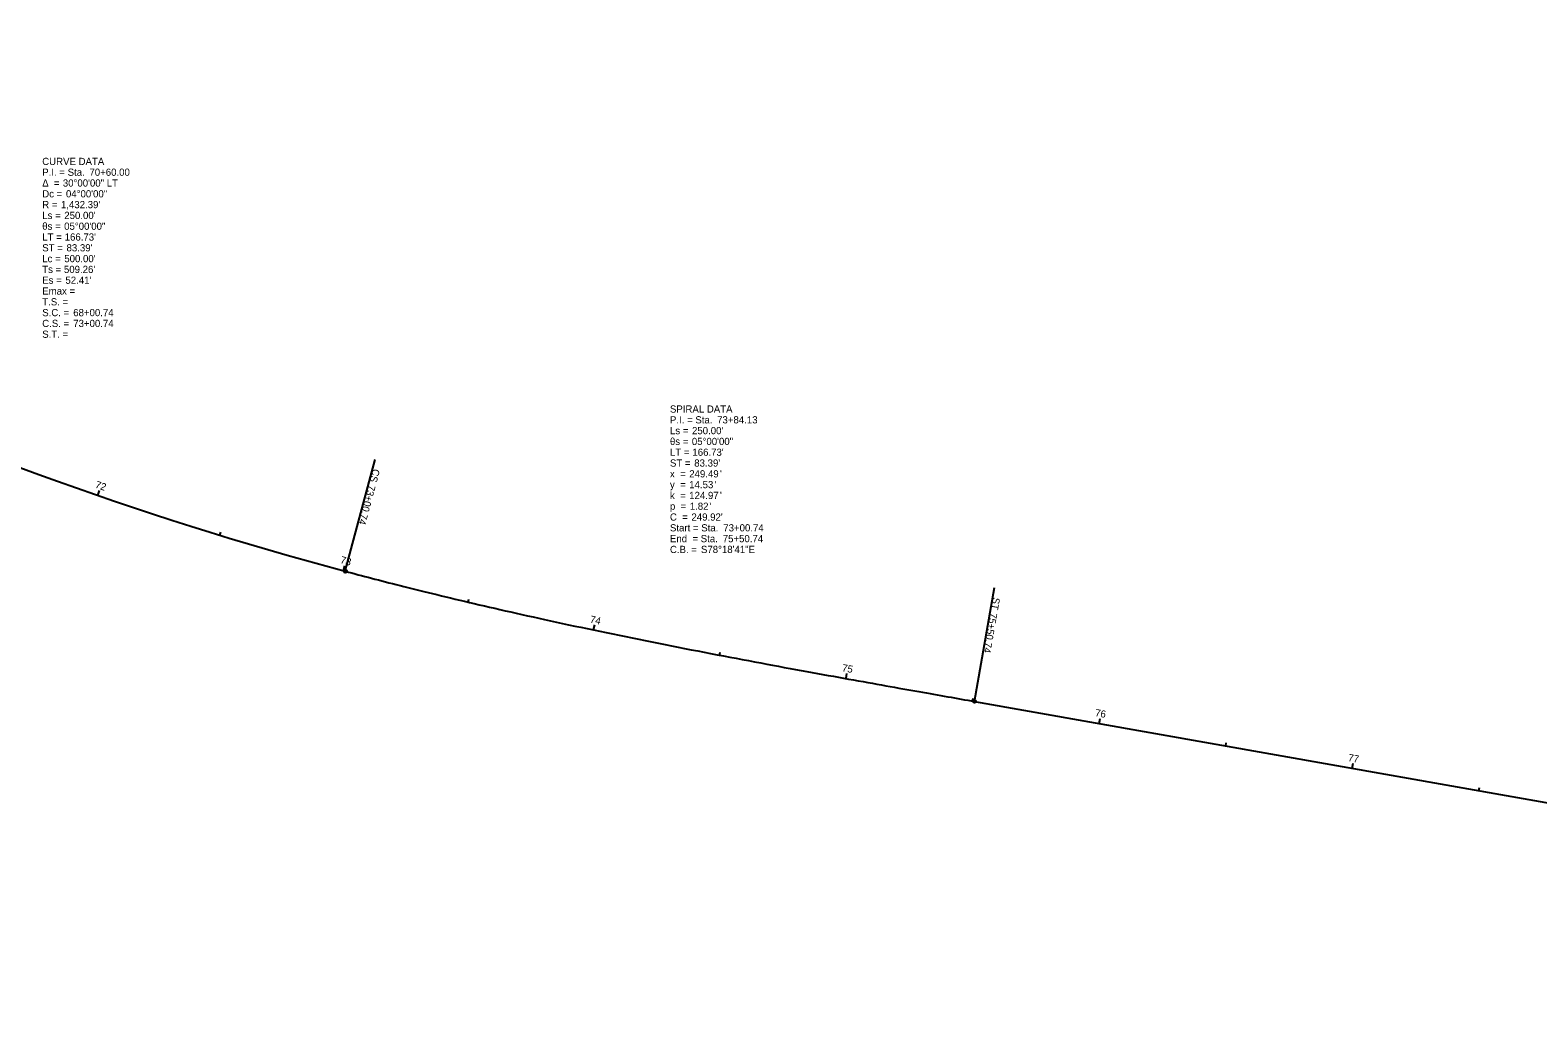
# Model space of a CAD drawing. Extents: x 1999336 to 2003366, y 252766 to 253936.
# Drawn here: x 1999900 to 2000486, y 253329 to 253714 of the extents above; entities that cross this region are included whole.
import ezdxf

# ---------------------------------------------------------------- set-up
doc = ezdxf.new("R2010")
doc.units = 0
for name, color, linetype in [('GE_X_CL_20', 7, 'Continuous'), ('GK_Visualization', 7, 'Continuous'), ('RW_X_Esmt_SH', 7, 'Continuous'), ('SC_Scratch3', 7, 'Continuous'), ('SV_X_Control_Cells_Found', 7, 'Continuous'), ('SV_X_Text_Elevation', 7, 'Continuous'), ('SV_X_Text_Name', 7, 'Continuous')]:
    doc.layers.add(name, color=color, linetype=linetype)

msp = doc.modelspace()

# ---------------------------------------------------------------- linework, layer by layer
at = {"layer": 'GE_X_CL_20'}
for p, q in [((2000022.52, 253503.8), (2000034.18, 253547.26)), ((1999926.22, 253533.31), (1999926.61, 253534.44)), ((2000021.81, 253503.99), (2000022.12, 253505.15)), ((2000267.25, 253453.17), (2000275.08, 253497.48)), ((2000119.11, 253480.97), (2000119.35, 253482.14)), ((2000217.3, 253462.06), (2000217.66, 253464.03)), ((2000315.76, 253444.6), (2000315.97, 253445.78)), ((2000414.24, 253427.2), (2000414.45, 253428.38))]:
    msp.add_line(p, q, dxfattribs=at)
for centre in [(2000022.52, 253503.8), (2000267.25, 253453.17)]:
    msp.add_circle(centre, 0.6, dxfattribs=at)
at = {"layer": 'GK_Visualization'}
msp.add_line((2000267.25, 253453.17), (2000967.83, 253329.36), dxfattribs=at)
msp.add_arc((2000393.78, 254887.24), 1432.39, 234.97811, 254.97808, dxfattribs=at)
msp.add_arc((2000393.78, 254887.24), 1432.39, 234.97811, 254.97808, dxfattribs=at)
msp.add_open_spline([(2000022.52, 253503.8), (2000029.23, 253502), (2000042.67, 253498.5), (2000069.64, 253491.85), (2000103.5, 253484.16), (2000144.3, 253475.72), (2000185.23, 253467.87), (2000219.39, 253461.66), (2000246.74, 253456.8), (2000260.41, 253454.38), (2000267.25, 253453.17)], degree=3, dxfattribs=at)
msp.add_open_spline([(2000022.52, 253503.8), (2000029.23, 253502), (2000042.67, 253498.5), (2000069.64, 253491.85), (2000103.5, 253484.16), (2000144.3, 253475.72), (2000185.23, 253467.87), (2000219.39, 253461.66), (2000246.74, 253456.8), (2000260.41, 253454.38), (2000267.25, 253453.17)], degree=3, dxfattribs=at)
at = {"layer": 'SC_Scratch3'}
for p, q in [((2000022.52, 253503.8), (2000034.18, 253547.26)), ((1999926.22, 253533.31), (1999926.88, 253535.2)), ((1999973.76, 253517.82), (1999974.11, 253518.96)), ((2000021.81, 253503.99), (2000022.33, 253505.92)), ((2000267.25, 253453.17), (2000275.08, 253497.48)), ((2000070.3, 253491.8), (2000070.57, 253492.97)), ((2000119.11, 253480.97), (2000119.52, 253482.93)), ((2000168.14, 253471.17), (2000168.36, 253472.35)), ((2000217.3, 253462.06), (2000217.66, 253464.03)), ((2000266.53, 253453.3), (2000266.74, 253454.48)), ((2000315.76, 253444.6), (2000316.11, 253446.57)), ((2000365, 253435.9), (2000365.21, 253437.08)), ((2000414.24, 253427.2), (2000414.59, 253429.16)), ((2000463.47, 253418.49), (2000463.68, 253419.68))]:
    msp.add_line(p, q, dxfattribs=at)
for centre in [(2000022.52, 253503.8), (2000267.25, 253453.17)]:
    msp.add_circle(centre, 0.6, dxfattribs=at)
at = {"layer": 'SV_X_Text_Name'}
for p, q in [((2000022.52, 253503.8), (2000034.18, 253547.26)), ((2000267.25, 253453.17), (2000275.08, 253497.48)), ((2000217.3, 253462.06), (2000217.51, 253463.24))]:
    msp.add_line(p, q, dxfattribs=at)
for centre in [(2000022.52, 253503.8), (2000267.25, 253453.17)]:
    msp.add_circle(centre, 0.6, dxfattribs=at)

# ---------------------------------------------------------------- texts
at = {"layer": 'GE_X_CL_20'}
for s, rotation, p in [('CS', 254.97808, (2000033.31, 253543.82)), ('73+00.74', 254.97808, (2000031.62, 253537.52)), ('ST', 259.97809, (2000274.47, 253493.76)), ('75+50.74', 259.97809, (2000273.41, 253487.77)), ('75', 349.77215, (2000215.58, 253464.96))]:
    msp.add_text(s, height=2.8, rotation=rotation, dxfattribs=at).set_placement(p)
at = {"layer": 'RW_X_Esmt_SH'}
for s, p in [('CURVE DATA', (1999904.61, 253661.78)), ('P.I. = Sta. ', (1999904.61, 253657.58)), ('70+60.00', (1999922.97, 253657.58)), ('Δ  = ', (1999904.61, 253653.38)), ('30°00\'00" LT', (1999912.63, 253653.38)), ('Dc = ', (1999904.61, 253649.18)), ('04°00\'00"', (1999913.84, 253649.18)), ('R = ', (1999904.61, 253644.98)), ('Ls = ', (1999904.61, 253640.78)), ("1,432.39'", (1999911.89, 253644.98)), ("250.00'", (1999913.19, 253640.78)), ('θs = ', (1999904.61, 253636.58)), ('05°00\'00"', (1999913.14, 253636.58)), ('ST = ', (1999904.61, 253628.18)), ('LT = ', (1999904.61, 253632.38)), ("166.73'", (1999913.34, 253632.38)), ("83.39'", (1999914.06, 253628.18)), ('Lc = ', (1999904.61, 253623.98)), ("500.00'", (1999913.19, 253623.98)), ('Ts = ', (1999904.61, 253619.78)), ("509.26'", (1999913.05, 253619.78)), ('Es = ', (1999904.61, 253615.58)), ('Emax = ', (1999904.61, 253611.38)), ("52.41'", (1999913.63, 253615.58)), ('T.S. = ', (1999904.61, 253607.18)), ('S.C. = ', (1999904.61, 253602.98)), ('C.S. = ', (1999904.61, 253598.78)), ('68+00.74', (1999916.67, 253602.98)), ('73+00.74', (1999916.67, 253598.78)), ('S.T. = ', (1999904.61, 253594.58)), ('SPIRAL DATA', (2000148.8, 253565.49)), ('P.I. = Sta. ', (2000148.8, 253561.29)), ('73+84.13', (2000167.16, 253561.29)), ('θs = ', (2000148.8, 253552.89)), ('Ls = ', (2000148.8, 253557.09)), ('05°00\'00"', (2000157.33, 253552.89)), ("250.00'", (2000157.38, 253557.09)), ('LT = ', (2000148.8, 253548.69)), ("166.73'", (2000157.53, 253548.69)), ('ST = ', (2000148.8, 253544.49)), ('249.49', (2000156.3, 253540.29)), ("83.39'", (2000158.25, 253544.49)), ("'", (2000168.25, 253540.29)), ('y  = ', (2000148.8, 253536.09)), ('x  = ', (2000148.8, 253540.29)), ('14.53', (2000156.3, 253536.09)), ("'", (2000166.08, 253536.09)), ('k  = ', (2000148.8, 253531.89)), ('124.97', (2000156.3, 253531.89)), ("'", (2000168.25, 253531.89)), ('C  = ', (2000148.8, 253523.49)), ('p  = ', (2000148.8, 253527.69)), ('1.82', (2000156.51, 253527.69)), ("249.92'", (2000157.16, 253523.49)), ("'", (2000164.12, 253527.69)), ('Start = Sta. ', (2000148.8, 253519.29)), ('73+00.74', (2000169.55, 253519.29)), ('C.B. = ', (2000148.8, 253510.89)), ('End  = Sta. ', (2000148.8, 253515.09)), ('S78°18\'41"E', (2000160.86, 253510.89)), ('75+50.74', (2000169.34, 253515.09))]:
    msp.add_text(s, height=2.8, dxfattribs=at).set_placement(p)
at = {"layer": 'SC_Scratch3'}
for s, rotation, p in [('CS', 254.97808, (2000033.31, 253543.82)), ('72', 340.94856, (1999924.97, 253536.39)), ('73+00.74', 254.97808, (2000031.62, 253537.52)), ('73', 344.94857, (2000020.37, 253507.02)), ('ST', 259.97809, (2000274.47, 253493.76)), ('74', 348.16034, (2000117.52, 253483.86)), ('75+50.74', 259.97809, (2000273.41, 253487.77)), ('75', 349.77215, (2000215.58, 253464.96)), ('76', 349.97809, (2000314.04, 253447.49)), ('77', 349.97809, (2000412.46, 253430.05))]:
    msp.add_text(s, height=2.8, rotation=rotation, dxfattribs=at).set_placement(p)
at = {"layer": 'SV_X_Control_Cells_Found'}
for s, p in [('CURVE DATA', (1999904.61, 253661.78)), ('P.I. = Sta. ', (1999904.61, 253657.58)), ('70+60.00', (1999922.97, 253657.58)), ('Δ  = ', (1999904.61, 253653.38)), ('30°00\'00" LT', (1999912.63, 253653.38)), ('Dc = ', (1999904.61, 253649.18)), ('04°00\'00"', (1999913.84, 253649.18)), ('R = ', (1999904.61, 253644.98)), ('Ls = ', (1999904.61, 253640.78)), ("1,432.39'", (1999911.89, 253644.98)), ("250.00'", (1999913.19, 253640.78)), ('θs = ', (1999904.61, 253636.58)), ('05°00\'00"', (1999913.14, 253636.58)), ('ST = ', (1999904.61, 253628.18)), ('LT = ', (1999904.61, 253632.38)), ("166.73'", (1999913.34, 253632.38)), ("83.39'", (1999914.06, 253628.18)), ('Lc = ', (1999904.61, 253623.98)), ("500.00'", (1999913.19, 253623.98)), ('Ts = ', (1999904.61, 253619.78)), ("509.26'", (1999913.05, 253619.78)), ('Es = ', (1999904.61, 253615.58)), ('Emax = ', (1999904.61, 253611.38)), ("52.41'", (1999913.63, 253615.58)), ('T.S. = ', (1999904.61, 253607.18)), ('S.C. = ', (1999904.61, 253602.98)), ('C.S. = ', (1999904.61, 253598.78)), ('68+00.74', (1999916.67, 253602.98)), ('73+00.74', (1999916.67, 253598.78)), ('S.T. = ', (1999904.61, 253594.58)), ('SPIRAL DATA', (2000148.8, 253565.49)), ('P.I. = Sta. ', (2000148.8, 253561.29)), ('73+84.13', (2000167.16, 253561.29)), ('θs = ', (2000148.8, 253552.89)), ('Ls = ', (2000148.8, 253557.09)), ('05°00\'00"', (2000157.33, 253552.89)), ("250.00'", (2000157.38, 253557.09)), ('LT = ', (2000148.8, 253548.69)), ("166.73'", (2000157.53, 253548.69)), ('ST = ', (2000148.8, 253544.49)), ('249.49', (2000156.3, 253540.29)), ("83.39'", (2000158.25, 253544.49)), ("'", (2000168.25, 253540.29)), ('y  = ', (2000148.8, 253536.09)), ('x  = ', (2000148.8, 253540.29)), ('14.53', (2000156.3, 253536.09)), ("'", (2000166.08, 253536.09)), ('k  = ', (2000148.8, 253531.89)), ('124.97', (2000156.3, 253531.89)), ("'", (2000168.25, 253531.89)), ('C  = ', (2000148.8, 253523.49)), ('p  = ', (2000148.8, 253527.69)), ('1.82', (2000156.51, 253527.69)), ("249.92'", (2000157.16, 253523.49)), ("'", (2000164.12, 253527.69)), ('Start = Sta. ', (2000148.8, 253519.29)), ('73+00.74', (2000169.55, 253519.29)), ('C.B. = ', (2000148.8, 253510.89)), ('End  = Sta. ', (2000148.8, 253515.09)), ('S78°18\'41"E', (2000160.86, 253510.89)), ('75+50.74', (2000169.34, 253515.09))]:
    msp.add_text(s, height=2.8, dxfattribs=at).set_placement(p)
at = {"layer": 'SV_X_Text_Elevation'}
for s, p in [('CURVE DATA', (1999904.61, 253661.78)), ('P.I. = Sta. ', (1999904.61, 253657.58)), ('70+60.00', (1999922.97, 253657.58)), ('Δ  = ', (1999904.61, 253653.38)), ('30°00\'00" LT', (1999912.63, 253653.38)), ('Dc = ', (1999904.61, 253649.18)), ('04°00\'00"', (1999913.84, 253649.18)), ('R = ', (1999904.61, 253644.98)), ('Ls = ', (1999904.61, 253640.78)), ("1,432.39'", (1999911.89, 253644.98)), ("250.00'", (1999913.19, 253640.78)), ('θs = ', (1999904.61, 253636.58)), ('05°00\'00"', (1999913.14, 253636.58)), ('ST = ', (1999904.61, 253628.18)), ('LT = ', (1999904.61, 253632.38)), ("166.73'", (1999913.34, 253632.38)), ("83.39'", (1999914.06, 253628.18)), ('Lc = ', (1999904.61, 253623.98)), ("500.00'", (1999913.19, 253623.98)), ('Ts = ', (1999904.61, 253619.78)), ("509.26'", (1999913.05, 253619.78)), ('Es = ', (1999904.61, 253615.58)), ('Emax = ', (1999904.61, 253611.38)), ("52.41'", (1999913.63, 253615.58)), ('T.S. = ', (1999904.61, 253607.18)), ('S.C. = ', (1999904.61, 253602.98)), ('C.S. = ', (1999904.61, 253598.78)), ('68+00.74', (1999916.67, 253602.98)), ('73+00.74', (1999916.67, 253598.78)), ('S.T. = ', (1999904.61, 253594.58)), ('SPIRAL DATA', (2000148.8, 253565.49)), ('P.I. = Sta. ', (2000148.8, 253561.29)), ('73+84.13', (2000167.16, 253561.29)), ('θs = ', (2000148.8, 253552.89)), ('Ls = ', (2000148.8, 253557.09)), ('05°00\'00"', (2000157.33, 253552.89)), ("250.00'", (2000157.38, 253557.09)), ('LT = ', (2000148.8, 253548.69)), ("166.73'", (2000157.53, 253548.69)), ('ST = ', (2000148.8, 253544.49)), ('249.49', (2000156.3, 253540.29)), ("83.39'", (2000158.25, 253544.49)), ("'", (2000168.25, 253540.29)), ('y  = ', (2000148.8, 253536.09)), ('x  = ', (2000148.8, 253540.29)), ('14.53', (2000156.3, 253536.09)), ("'", (2000166.08, 253536.09)), ('k  = ', (2000148.8, 253531.89)), ('124.97', (2000156.3, 253531.89)), ("'", (2000168.25, 253531.89)), ('C  = ', (2000148.8, 253523.49)), ('p  = ', (2000148.8, 253527.69)), ('1.82', (2000156.51, 253527.69)), ("249.92'", (2000157.16, 253523.49)), ("'", (2000164.12, 253527.69)), ('Start = Sta. ', (2000148.8, 253519.29)), ('73+00.74', (2000169.55, 253519.29)), ('C.B. = ', (2000148.8, 253510.89)), ('End  = Sta. ', (2000148.8, 253515.09)), ('S78°18\'41"E', (2000160.86, 253510.89)), ('75+50.74', (2000169.34, 253515.09))]:
    msp.add_text(s, height=2.8, dxfattribs=at).set_placement(p)
at = {"layer": 'SV_X_Text_Name'}
for s, rotation, p in [('CS', 254.97808, (2000033.31, 253543.82)), ('73+00.74', 254.97808, (2000031.62, 253537.52)), ('ST', 259.97809, (2000274.47, 253493.76)), ('75+50.74', 259.97809, (2000273.41, 253487.77))]:
    msp.add_text(s, height=2.8, rotation=rotation, dxfattribs=at).set_placement(p)

doc.saveas('drawing.dxf')
